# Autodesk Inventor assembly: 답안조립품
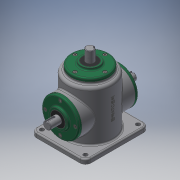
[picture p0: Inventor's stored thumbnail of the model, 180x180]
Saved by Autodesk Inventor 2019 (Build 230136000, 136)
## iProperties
Created: 2020-12
Part Number: 답안조립품
Material: 일반
Document SubType Name: Assembly
Designer: jun-1-6
Author: jun-1-6
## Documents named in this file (16)
- C:\Users\jun-1-6\Desktop\701207V1003\답안조립품.iam
- C:\Users\jun-1-6\Desktop\701207V1003\본체.ipt
- C:\Users\jun-1-6\Desktop\701207V1003\메인 베벨기어.ipt
- C:\Users\jun-1-6\Desktop\701207V1003\메인 축.ipt
- 메인 축.ipt
- C:\Users\jun-1-6\Desktop\701207V1003\베어링 6203.ipt
- C:\Users\jun-1-6\Desktop\701207V1003\볼트 M4.ipt
- 볼트 M4.ipt
- C:\Users\jun-1-6\Desktop\701207V1003\서브 베벨기어.ipt
- C:\Users\jun-1-6\Desktop\701207V1003\서브 축.ipt
- 서브 축.ipt
- C:\Users\jun-1-6\Desktop\701207V1003\오일 실.ipt
- 오일 실.ipt
- C:\Users\jun-1-6\Desktop\701207V1003\커버.ipt
- C:\Users\jun-1-6\Desktop\701207V1003\키 4x4.ipt
- C:\Users\jun-1-6\Desktop\701207V1003\키 5x5.ipt
## Named parameters: d11_d2 = 0, d12_d3 = 0, d13_d4 = 0, d14_d5 = 180 deg, d15_d6 = 0, d16_d7 = 0, d17_d8 = 0, d18_d9 = 0, d19_d10 = 0, d20_d0 = 0, d21_d1 = 0
